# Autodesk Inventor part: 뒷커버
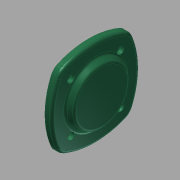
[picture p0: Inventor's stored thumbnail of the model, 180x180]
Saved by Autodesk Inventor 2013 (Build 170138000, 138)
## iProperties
Created: 2015-11
Part Number: 뒷커버
Material: 일반
Document SubType Name: Modeling
Designer: mduedu
Density: 2.71 g/cm^3
Author: mduedu
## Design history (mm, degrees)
sketch "스케치1"
  geometry: L1 (50, 50)-(-50, 50); L2 (-50, 50)-(-50, -50); L3 (-50, -50)-(50, -50); L4 (50, -50)-(50, 50); L5 (0, 50)-(0, -50); L6 (50, 0)-(-50, 0); A1 r 90 centre (-40, 0) between (40.415, -40.415) and (40.415, 40.415); A2 r 90 centre (40, 0) between (-40.415, 40.415) and (-40.415, -40.415); A3 r 90 centre (0, -40) between (40.415, 40.415) and (-40.415, 40.415); A4 r 90 centre (0, 40) between (-40.415, -40.415) and (40.415, -40.415); 2 further points
  constraints: 12 end point, 8 point on circle, 5 midpoint, 4 centre point, 2 horizontal alignment, 2 parallel, 2 perpendicular, 2 symmetric about line, 2 tangent, 2 vertical alignment, 1 equal radius, 1 horizontal, 2 other
  dimensions: "d0" = 100 distance of L3.end L1.start; "d2" = 90 radius of A1
extrude "돌출1" new body sketch "스케치1" distance "d3" = 8; taper "d4" = 0 deg
sketch "스케치2"
  geometry: C1 r 35 at (0, 0); 1 further point
  constraints: 1 centre point, 1 coincident
  dimensions: "d5" = 70 diameter of C1
extrude "돌출2" join sketch "스케치2" distance "d6" = 7; taper "d7" = -30 deg
sketch "스케치3"
  geometry: L1 (0, 0)-(0, 40); L2 (0, 0)-(-28.284, 28.284); A1 r 40 centre (0, 0) between (0, 40) and (-28.284, 28.284); 2 further points
  constraints: 4 end point, 2 coincident, 2 point on circle, 1 centre point, 1 vertical
  dimensions: "d8" = 80 diameter of A1; "d9" = 45 deg angle of L1 L2
hole "구멍1" sketch "스케치3" at (-28.284, 28.284) diameter "d11" = 4.5; stored, may be unused: countersink angle "d15" = 90 deg, drill point angle "d17" = 118 deg; dims "d12" = 6, "d13" = 8, "d14" = 4.4, "d16" = 8
sketch "스케치4"
  geometry: C1 r 35 at (0, 0); 1 further point
  constraints: 1 centre point, 1 coincident
  dimensions: "d21" = 70 diameter of C1
extrude "돌출3" join sketch "스케치4" distance "d23" = 12; taper "d24" = 0 deg
hole "구멍2" diameter "d27" = 30; stored, may be unused: countersink angle "d31" = 90 deg, drill point angle "d33" = 0 deg; dims "d25" = 10, "d26" = 10, "d28" = 6, "d29" = 40, "d30" = 12, "d32" = 15
fillet "모깎기2" dims "d35" = 15
fillet "모깎기3" dims "d36" = 3
fillet "모깎기4" dims "d37" = 3
fillet "모깎기5" dims "d38" = 0.3
chamfer "모따기1" distance "d39" = 1; stored, may be unused: second distance "d40" = 2, angle "d41" = 45 deg
node "솔리드1"
pattern_circular "원형 패턴1" dims angle "d19" = 360 deg
